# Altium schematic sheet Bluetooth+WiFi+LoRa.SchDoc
size A4; SheetNumber: 2; SheetTotal: 2
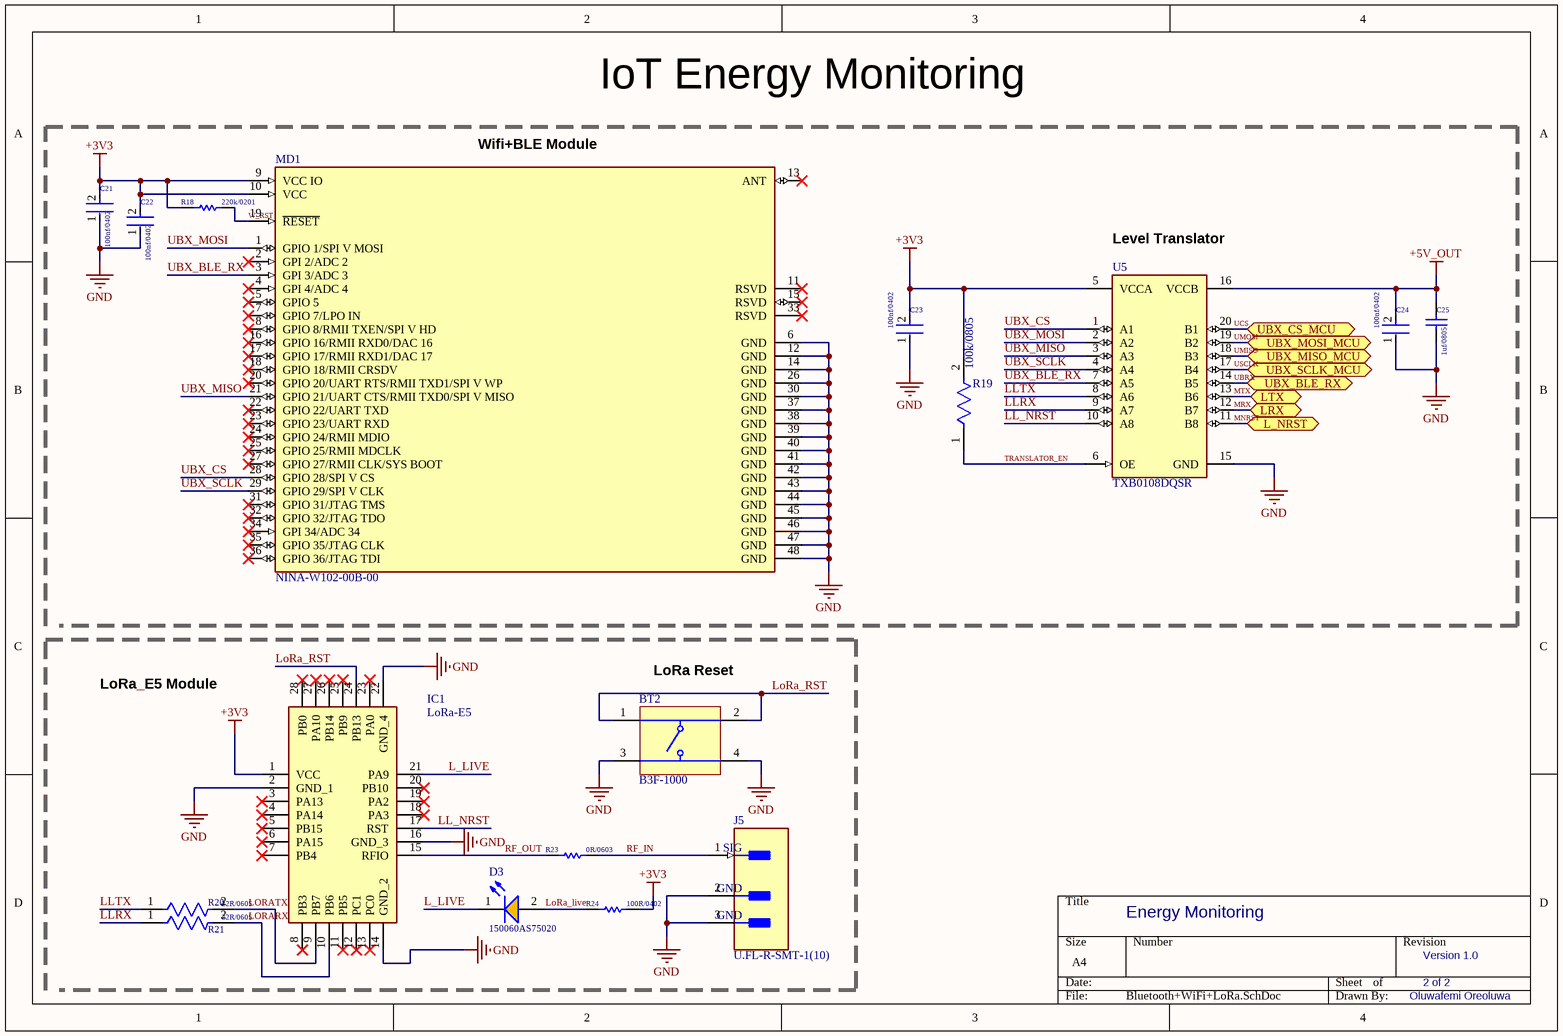
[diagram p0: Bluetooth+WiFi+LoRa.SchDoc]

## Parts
BT2  B3F-1000  [OMRON-B3F-1000-4_V]
C21  100nf/0402  [FP-GRM15-MFG]
C22  100nf/0402  [FP-GRM15-MFG]
C23  100nf/0402  [FP-GRM15-MFG]
C24  100nf/0402  [FP-GRM15-MFG]
C25  1uf/0805  [CAPC2013X140X50LL20T25]
D3  150060AS75020  [WL-SMCW_0603_150060xx75020]
IC1  LoRa-E5  [LoRaE5]
J5  U.FL-R-SMT-1(10)  [FP-U_FL-R-SMT-1_10-MFG]
MD1  NINA-W102-00B-00  [FP-NINA-W102-00B-00-MFG]
R18  220k/0201  [RESC0603X26X15ML03T05]
R19  100k/0805  [FP-RN732A-MFG]
R20  22R/0605  [FP-CPF0603-MFG]
R21  22R/0605  [FP-CPF0603-MFG]
R23  0R/0603  [RESC1608X55X25ML10T15]
R24  100R/0402  [RESC1005X40X25LL05T05]
U5  TXB0108DQSR  [FP-DQS0020A-MFG]

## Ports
L_NRST (bidir, see MCU+PWR+USB+SPORT[1B]), LRX (bidir, see MCU+PWR+USB+SPORT[3B]), LTX (bidir, see MCU+PWR+USB+SPORT[3B]), UBX_BLE_RX (bidir, see MCU+PWR+USB+SPORT[3B]), UBX_CS_MCU (bidir, see MCU+PWR+USB+SPORT[3B]), UBX_MISO_MCU (bidir, see MCU+PWR+USB+SPORT[3B]), UBX_MOSI_MCU (bidir, see MCU+PWR+USB+SPORT[3B]), UBX_SCLK_MCU (bidir, see MCU+PWR+USB+SPORT[3B])

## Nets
+3V3: C21.2 C22.2 C23.2 IC1.1(VCC) MD1.9(VCC_IO) MD1.10(VCC) R18.1 R19.2 R24.2 U5.5(VCCA)
+5V_OUT: C24.2 C25.2 U5.16(VCCB)
GND: BT2.3 BT2.4 C21.1 C22.1 C23.1 C24.1 C25.1 IC1.2(GND_1) IC1.14(GND_2) IC1.16(GND_3) IC1.22(GND_4) J5.2(GND) J5.3(GND) MD1.6(GND) MD1.12(GND) MD1.14(GND) MD1.26(GND) MD1.30(GND) MD1.37(GND) MD1.38(GND) MD1.39(GND) MD1.40(GND) MD1.41(GND) MD1.42(GND) MD1.43(GND) MD1.44(GND) MD1.45(GND) MD1.46(GND) MD1.47(GND) MD1.48(GND) U5.15(GND)
L_LIVE: D3.1(K) IC1.21(PA9)
LL_NRST: IC1.17(RST) U5.10(A8)
LLRX: R21.1 U5.9(A7)
LLTX: R20.1 U5.8(A6)
LoRa_live: D3.2(A) R24.1
LoRa_RST: BT2.1 BT2.2 IC1.24(PB13)
LORARX: IC1.10(PB6) R21.2
LORATX: IC1.9(PB7) R20.2
MNRST: U5.11(B8) ; port L_NRST
MRX: U5.12(B7) ; port LRX
MTX: U5.13(B6) ; port LTX
RF_IN: J5.1(SIG) R23.2
RF_OUT: IC1.15(RFIO) R23.1
TRANSLATOR_EN: R19.1 U5.6(OE)
UBRX: U5.14(B5) ; port UBX_BLE_RX
UBX_BLE_RX: MD1.3(GPI_3/ADC_3) U5.7(A5)
UBX_CS: MD1.28(GPIO_28/SPI_V_CS) U5.1(A1)
UBX_MISO: MD1.21(GPIO_21/UART_CTS/RMII_TXD0/SPI_V_MISO) U5.3(A3)
UBX_MOSI: MD1.1(GPIO_1/SPI_V_MOSI) U5.2(A2)
UBX_SCLK: MD1.29(GPIO_29/SPI_V_CLK) U5.4(A4)
UCS: U5.20(B1) ; port UBX_CS_MCU
UMISO: U5.18(B3) ; port UBX_MISO_MCU
UMOSI: U5.19(B2) ; port UBX_MOSI_MCU
USCLK: U5.17(B4) ; port UBX_SCLK_MCU
W_RST: MD1.19(~{RESET}) R18.2

Not connected (* = marked no-connect by the designer): IC1 3(PA13)* 4(PA14)* 5(PB15)* 6(PA15)* 7(PB4)* 8(PB3)* 11(PB5)* 12(PC1)* 13(PC0)* 18(PA3)* 19(PA2)* 20(PB10)* 23(PA0)* 25(PB9)* 26(PB14)* 27(PA10)* 28(PB0)*; MD1 2(GPI_2/ADC_2)* 4(GPI_4/ADC_4)* 5(GPIO_5)* 7(GPIO_7/LPO_IN)* 8(GPIO_8/RMII_TXEN/SPI_V_HD)* 11(RSVD)* 13(ANT)* 15(RSVD)* 16(GPIO_16/RMII_RXD0/DAC_16)* 17(GPIO_17/RMII_RXD1/DAC_17)* 18(GPIO_18/RMII_CRSDV)* 20(GPIO_20/UART_RTS/RMII_TXD1/SPI_V_WP)* 22(GPIO_22/UART_TXD)* 23(GPIO_23/UART_RXD)* 24(GPIO_24/RMII_MDIO)* 25(GPIO_25/RMII_MDCLK)* 27(GPIO_27/RMII_CLK/SYS_BOOT)* 31(GPIO_31/JTAG_TMS)* 32(GPIO_32/JTAG_TDO)* 33(RSVD)* 34(GPI_34/ADC_34)* 35(GPIO_35/JTAG_CLK)* 36(GPIO_36/JTAG_TDI)*

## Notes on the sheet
- IoT Energy Monitoring
- (near MD1) Wifi+BLE Module
- (near U5) Level Translator
- LoRa_E5 Module
- (near BT2) LoRa Reset
- Energy Monitoring
- Version 1.0
- 2 of 2
- Oluwafemi Oreoluwa

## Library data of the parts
BT2 = CMP-1677-00002-1: Tactile Switch, SPST-NO, 0.05 A, 5 to 24 V, -25 to 70 degC, 4-Pin THD, RoHS, Bulk; Shielding: Shielded; Gender: Female; Capacitance: -45 f; Voltage Rating: 150 V; Current Rating: 1.5 A
C21-C24 = CMP-2100-03641-2: CAP CER 0.1UF 16V X7R 0402; Manufacturer Part Number: GRM155R71C104KA88D; Manufacturer: Murata; Standoff Height: 0mm; Tolerance: 10%; Voltage Rating: 16Vdc; Material: Ceramic; Capacitance: 0.10μF; Value: 0.10μF
C25 = CMP-2007-03234-1: Part Number: C0805C105K3RACTU; Manufacturer: Kemet
D3 = CMP-03913-104891423-2: WL-SMCW SMT Mono-Color Chip LED Waterclear super f; Luminous Intensity: 140mcd; Max Reverse Voltage (DC): 5V; Peak Wavelength: 610nm; Forward Current: 60mA; Viewing Angle: 140°; Forward Voltage: 2V; Dominant Wavelength: 605nm
IC1 = LoRa-E5: Integrated Circuit; Manufacturer_Name: Seeed Studio
J5 = CMP-2000-05152-3: CONN U.FL RCPT STR 50 OHM SMD; Max Frequency: 6GHz; Connector Type: Coaxial; Body Plating: Silver; Body Material: Bronze; Impedance: 50R; Dielectric Material: Polymer; Insulation Resistance: 500MR; Gender: Male
MD1 = CMP-207130-000007-1: STAND-ALONE MULTIRADIO MODULES; Manufacturer: U-Blox; Max Supply Voltage: 3.6V; Number Of Adc Channels: 17; Receiving Current: 100-140mA; Nominal Supply Current: 30-190mA; Data Rate: 100Mbits/s; Max Frequency: 2.5GHz; Sensitivity: -96dBm; Min Supply Voltage: 3V; Interface: I2C,SPI,UART,CAN,Ethernet,I2S,Other; Bandwidth: 20MHz; Transmitting Current: 225-320mA; Number Of Gpio: 20
R18 = CMP-2004-03487-1: Manufacturer: Panasonic; Part Number: ERJ1GNF2203C
R19 = CMP-03211-002801-1: SMD Chip Resistor, Thin Film, 100KΩ, 100 V, 0805 [2012 Metric], 100 mW, 0.1%, RN73 Series; Manufacturer Part Number: RN73C2A100KBTDF; Manufacturer: TE Connectivity; Temperature Coefficient: 10ppm/°C; Voltage Rating: 100V; Power Rating: 0.1W
R20 R21 = CMP-03211-007811-1: RES SMD 22Ω 0.1% 1/16W 0603; Manufacturer: TE Connectivity; Manufacturer Part Number: CPF0603B22RE1; Temperature Coefficient: 25ppm/°C; Power Rating: 0.063W; Voltage Rating: 50V
R23 = CMP-2100-03667-1: Chip Resistor, 0 Ohm, +/- 5%, 0.1 W, -55 to 155 degC, 0603 (1608 Metric), RoHS, Tape and Reel; Manufacturer: Yageo; Temperature Coefficient: 200ppm/degreesC; Voltage Rating: 50V; Power Rating: 100mW; Resistance: 0mOhm
R24 = CMP-2002-00605-3: Chip Resistor, 100 Ohm, +/- 1%, 100 mW, -55 to 155 degC, 0402 (1005 Metric), RoHS, Tape and Reel; Manufacturer: Basic Passives; PartNumber: ERJ-2RKF1000X; Power Rating: 100 mW; Resistance: 100 Ohm; Voltage Rating: 50 V; Case\/Package: 0402
U5 = CMP-04899-000009-1: IC TRNSLTR BIDIRECTIONAL 20USON; Manufacturer: Texas Instruments; Nominal Supply Current: 0.05-3.5uA; Propagation Delay: 4ns; Max Supply Voltage: 5.5V; V A Min: 1.2V; Max Junction Temp: +150°C; Logic Function Desc: Non-Inverting; Number Of Inputs: 1; V A Max: 3.6V; Number Of Circuits: 8; V B Min: 1.65V; Standoff Height: 0mm; Data Rate: 100Mbits/s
